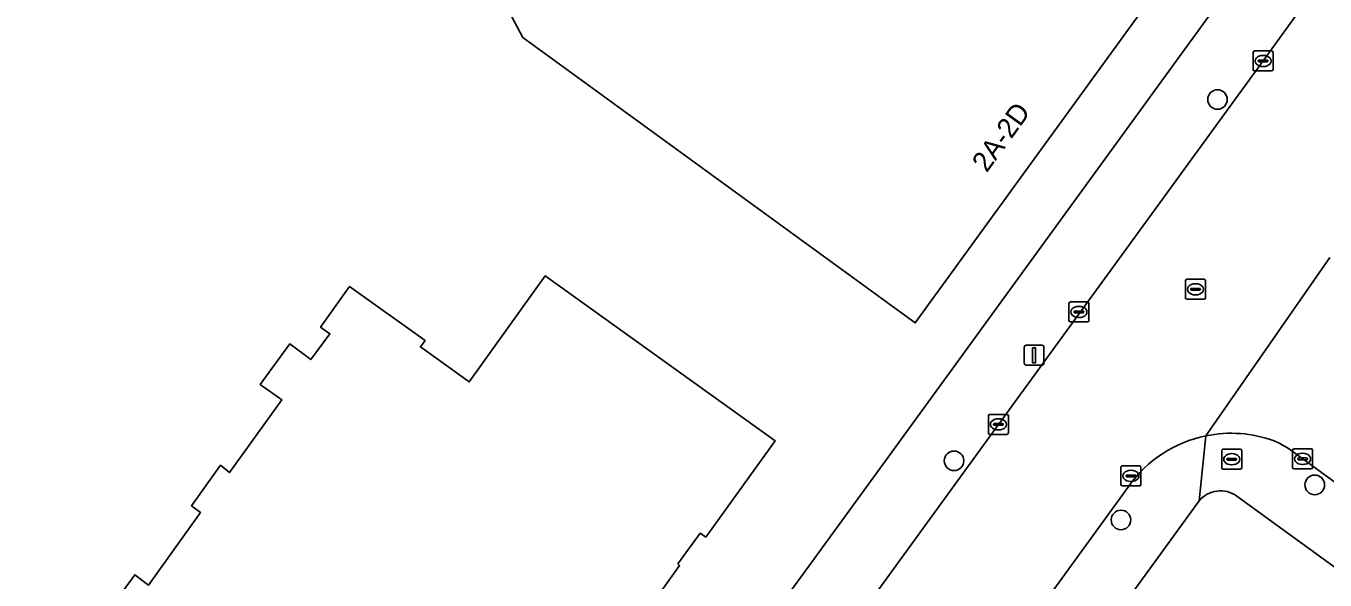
# Model space of a CAD drawing. Extents: x 159674 to 160531, y 382172 to 382904.
# Drawn here: x 160035.6 to 160100.6, y 382566.2 to 382593.8 of the extents above; entities that cross this region are included whole.
import ezdxf

# ---------------------------------------------------------------- set-up
doc = ezdxf.new("R2010")
doc.units = 0
for name, color, linetype in [('IMGEO_Boom', 7, 'Continuous'), ('IMGEO_Brandkraan', 7, 'Continuous'), ('IMGEO_Erf', 7, 'Continuous'), ('IMGEO_Kolk', 7, 'Continuous'), ('IMGEO_Lichtmast', 7, 'Continuous'), ('IMGEO_Pand', 7, 'Continuous'), ('IMGEO_Pand_nummerreeks', 7, 'Continuous'), ('IMGEO_Rijbaan_lokaal_open', 7, 'Continuous'), ('IMGEO_Rioolput', 7, 'Continuous'), ('IMGEO_Voetpad_open', 7, 'Continuous')]:
    doc.layers.add(name, color=color, linetype=linetype)

msp = doc.modelspace()

# ---------------------------------------------------------------- linework, layer by layer
at = {"layer": 'IMGEO_Boom'}
for centre in [(160095.183, 382590.164), (160082.011, 382572.108), (160100.046, 382570.904), (160090.355, 382569.153)]:
    msp.add_circle(centre, 0.489, dxfattribs=at)
at = {"layer": 'IMGEO_Brandkraan'}
for p, q in [((160095.469, 382572.687), (160096.321, 382572.687)), ((160095.394, 382571.761), (160095.394, 382572.613)), ((160095.653, 382572.181), (160095.653, 382572.193)), ((160096.091, 382572.144), (160095.693, 382572.144)), ((160095.696, 382572.23), (160096.094, 382572.23)), ((160095.882, 382572.467), (160095.907, 382572.467)), ((160096.137, 382572.193), (160096.137, 382572.181)), ((160096.395, 382572.613), (160096.395, 382571.761)), ((160096.321, 382571.687), (160095.469, 382571.687)), ((160095.905, 382571.907), (160095.88, 382571.907))]:
    msp.add_line(p, q, dxfattribs=at)
for points in [[(160095.469, 382572.687), (160096.321, 382572.687)], [(160095.394, 382571.761), (160095.394, 382572.613)], [(160096.395, 382572.613), (160096.395, 382571.761)], [(160096.321, 382571.687), (160095.469, 382571.687)]]:
    msp.add_lwpolyline(points, dxfattribs=at)
for centre, radius, start, end in [((160095.471, 382572.611), 0.0765, 91.55205, 178.44795), ((160095.471, 382572.611), 0.0765, 91.55205, 178.44795), ((160096.319, 382572.611), 0.0765, 1.55205, 88.44795), ((160096.319, 382572.611), 0.0765, 1.55205, 88.44795), ((160095.693, 382572.19), 0.0403, 85.87752, 175.75265), ((160095.69, 382572.18), 0.0366, 178.93798, 274.71019), ((160096.094, 382572.187), 0.043, 264.86636, 352.45326), ((160096.098, 382572.192), 0.0386, 1.73085, 96.63898), ((160095.471, 382571.763), 0.0765, 181.55205, 268.44795), ((160095.471, 382571.763), 0.0765, 181.55205, 268.44795), ((160096.319, 382571.763), 0.0765, 271.55205, 358.44795), ((160096.319, 382571.763), 0.0765, 271.55205, 358.44795)]:
    msp.add_arc(centre, radius, start, end, dxfattribs=at)
for centre, major_axis, ratio, start_param, end_param in [((160095.881, 382572.187), (-0.387, 0.002), 0.722429, 4.712389, 7.853982), ((160095.906, 382572.187), (-0.39, 0.002), 0.717154, 1.570796, 4.712389)]:
    msp.add_ellipse(centre, major_axis=major_axis, ratio=ratio, start_param=start_param, end_param=end_param, dxfattribs=at)
at = {"layer": 'IMGEO_Erf'}
for points in [[(159987.625, 382596.74), (159998.32, 382576.572), (160012.158, 382566.305), (160014.085, 382564.875), (160015.556, 382563.784), (160018.977, 382561.245), (160021.814, 382559.14), (160050.522, 382537.716), (160052.445, 382536.281), (160054.378, 382538.936), (160055.599, 382540.613), (160060.131, 382546.714), (160064.26, 382552.334), (160068.989, 382558.995), (160073.24, 382564.766), (160078.977, 382572.654), (160139.025, 382655.211)], [(160093.699, 382597.768), (160080.073, 382579.001), (160060.451, 382593.261), (160043.33, 382625.444)], [(160039.563, 382564.384), (160041.044, 382566.417), (160041.727, 382565.89), (160044.328, 382569.516), (160043.878, 382569.863), (160045.338, 382571.887), (160045.791, 382571.52), (160048.402, 382575.152), (160047.321, 382575.925), (160048.796, 382577.95), (160049.847, 382577.166), (160050.802, 382578.453), (160050.343, 382578.793), (160051.792, 382580.818), (160055.56, 382578.117), (160055.332, 382577.8), (160057.77, 382576.052), (160061.568, 382581.351), (160068.999, 382576.024), (160073.063, 382573.111), (160069.597, 382568.294), (160069.324, 382568.488), (160068.201, 382566.953), (160068.292, 382566.873), (160066.759, 382564.747)], [(160094.261, 382570.107), (160066.611, 382532.056)], [(160106.42, 382540.296), (160101.292, 382544.099), (160102.861, 382546.215), (160104.194, 382548.012), (160109.338, 382544.231), (160111.578, 382547.337), (160108.798, 382549.356), (160109.901, 382550.874), (160111.668, 382551.187), (160113.36, 382549.958), (160113.608, 382550.312), (160108.612, 382553.944), (160110.021, 382555.881), (160115.017, 382552.25), (160117.084, 382555.093), (160117.069, 382555.171), (160096.153, 382570.347)]]:
    msp.add_lwpolyline(points, dxfattribs=at)
msp.add_arc((160095.337, 382569.203), 1.405, 54.50552, 139.95319, dxfattribs=at)
at = {"layer": 'IMGEO_Kolk'}
for p, q in [((160096.962, 382591.663), (160096.962, 382592.515)), ((160097.037, 382592.589), (160097.889, 382592.589)), ((160097.45, 382592.369), (160097.475, 382592.369)), ((160097.963, 382592.515), (160097.963, 382591.663)), ((160097.889, 382591.589), (160097.037, 382591.589)), ((160097.221, 382592.083), (160097.221, 382592.095)), ((160097.659, 382592.046), (160097.261, 382592.046)), ((160097.264, 382592.132), (160097.662, 382592.132)), ((160097.473, 382591.809), (160097.448, 382591.809)), ((160097.705, 382592.095), (160097.705, 382592.083)), ((160087.755, 382579.121), (160087.755, 382579.973)), ((160087.83, 382580.047), (160088.682, 382580.047)), ((160088.243, 382579.827), (160088.268, 382579.827)), ((160088.756, 382579.973), (160088.756, 382579.121)), ((160088.014, 382579.541), (160088.014, 382579.553)), ((160088.452, 382579.504), (160088.054, 382579.504)), ((160088.057, 382579.59), (160088.455, 382579.59)), ((160088.266, 382579.267), (160088.241, 382579.267)), ((160088.498, 382579.553), (160088.498, 382579.541)), ((160088.682, 382579.047), (160087.83, 382579.047)), ((160083.728, 382573.502), (160083.728, 382574.354)), ((160083.803, 382574.428), (160084.655, 382574.428)), ((160084.216, 382574.208), (160084.241, 382574.208)), ((160084.729, 382574.354), (160084.729, 382573.502)), ((160084.655, 382573.428), (160083.803, 382573.428)), ((160083.987, 382573.922), (160083.987, 382573.934)), ((160084.425, 382573.885), (160084.027, 382573.885)), ((160084.03, 382573.971), (160084.428, 382573.971)), ((160084.239, 382573.648), (160084.214, 382573.648)), ((160084.471, 382573.934), (160084.471, 382573.922)), ((160099.013, 382572.705), (160099.865, 382572.705)), ((160098.938, 382571.779), (160098.938, 382572.631)), ((160099.197, 382572.199), (160099.197, 382572.211)), ((160099.635, 382572.162), (160099.237, 382572.162)), ((160099.24, 382572.248), (160099.638, 382572.248)), ((160099.426, 382572.485), (160099.451, 382572.485)), ((160099.681, 382572.211), (160099.681, 382572.199)), ((160099.939, 382572.631), (160099.939, 382571.779)), ((160090.354, 382570.929), (160090.354, 382571.781)), ((160090.429, 382571.855), (160091.281, 382571.855)), ((160090.656, 382571.398), (160091.054, 382571.398)), ((160090.842, 382571.635), (160090.867, 382571.635)), ((160091.355, 382571.781), (160091.355, 382570.929)), ((160099.865, 382571.705), (160099.013, 382571.705)), ((160099.449, 382571.925), (160099.424, 382571.925)), ((160091.281, 382570.855), (160090.429, 382570.855)), ((160090.613, 382571.349), (160090.613, 382571.361)), ((160091.051, 382571.312), (160090.653, 382571.312)), ((160090.865, 382571.075), (160090.84, 382571.075)), ((160091.097, 382571.361), (160091.097, 382571.349))]:
    msp.add_line(p, q, dxfattribs=at)
for points in [[(160096.962, 382591.663), (160096.962, 382592.515)], [(160097.037, 382592.589), (160097.889, 382592.589)], [(160097.963, 382592.515), (160097.963, 382591.663)], [(160097.889, 382591.589), (160097.037, 382591.589)], [(160087.755, 382579.121), (160087.755, 382579.973)], [(160087.83, 382580.047), (160088.682, 382580.047)], [(160088.756, 382579.973), (160088.756, 382579.121)], [(160088.682, 382579.047), (160087.83, 382579.047)], [(160083.728, 382573.502), (160083.728, 382574.354)], [(160083.803, 382574.428), (160084.655, 382574.428)], [(160084.729, 382574.354), (160084.729, 382573.502)], [(160084.655, 382573.428), (160083.803, 382573.428)], [(160099.013, 382572.705), (160099.865, 382572.705)], [(160098.938, 382571.779), (160098.938, 382572.631)], [(160099.939, 382572.631), (160099.939, 382571.779)], [(160090.354, 382570.929), (160090.354, 382571.781)], [(160090.429, 382571.855), (160091.281, 382571.855)], [(160091.355, 382571.781), (160091.355, 382570.929)], [(160099.865, 382571.705), (160099.013, 382571.705)], [(160091.281, 382570.855), (160090.429, 382570.855)]]:
    msp.add_lwpolyline(points, dxfattribs=at)
for centre, radius, start, end in [((160097.039, 382592.513), 0.0765, 91.55205, 178.44795), ((160097.039, 382592.513), 0.0765, 91.55205, 178.44795), ((160097.887, 382592.513), 0.0765, 1.55205, 88.44795), ((160097.887, 382592.513), 0.0765, 1.55205, 88.44795), ((160097.039, 382591.665), 0.0765, 181.55205, 268.44795), ((160097.039, 382591.665), 0.0765, 181.55205, 268.44795), ((160097.261, 382592.092), 0.0403, 85.87752, 175.75265), ((160097.258, 382592.082), 0.0366, 178.93798, 274.71019), ((160097.662, 382592.089), 0.043, 264.86636, 352.45326), ((160097.666, 382592.094), 0.0386, 1.73085, 96.63898), ((160097.887, 382591.665), 0.0765, 271.55205, 358.44795), ((160097.887, 382591.665), 0.0765, 271.55205, 358.44795), ((160087.832, 382579.971), 0.0765, 91.55205, 178.44795), ((160087.832, 382579.971), 0.0765, 91.55205, 178.44795), ((160088.68, 382579.971), 0.0765, 1.55205, 88.44795), ((160088.68, 382579.971), 0.0765, 1.55205, 88.44795), ((160088.054, 382579.55), 0.0403, 85.87752, 175.75265), ((160088.051, 382579.54), 0.0366, 178.93798, 274.71019), ((160088.455, 382579.547), 0.043, 264.86636, 352.45326), ((160088.459, 382579.552), 0.0386, 1.73085, 96.63898), ((160087.832, 382579.123), 0.0765, 181.55205, 268.44795), ((160087.832, 382579.123), 0.0765, 181.55205, 268.44795), ((160088.68, 382579.123), 0.0765, 271.55205, 358.44795), ((160088.68, 382579.123), 0.0765, 271.55205, 358.44795), ((160083.805, 382574.352), 0.0765, 91.55205, 178.44795), ((160083.805, 382574.352), 0.0765, 91.55205, 178.44795), ((160084.653, 382574.352), 0.0765, 1.55205, 88.44795), ((160084.653, 382574.352), 0.0765, 1.55205, 88.44795), ((160083.805, 382573.504), 0.0765, 181.55205, 268.44795), ((160083.805, 382573.504), 0.0765, 181.55205, 268.44795), ((160084.027, 382573.931), 0.0403, 85.87752, 175.75265), ((160084.024, 382573.921), 0.0366, 178.93798, 274.71019), ((160084.428, 382573.928), 0.043, 264.86636, 352.45326), ((160084.432, 382573.933), 0.0386, 1.73085, 96.63898), ((160084.653, 382573.504), 0.0765, 271.55205, 358.44795), ((160084.653, 382573.504), 0.0765, 271.55205, 358.44795), ((160099.015, 382572.629), 0.0765, 91.55205, 178.44795), ((160099.015, 382572.629), 0.0765, 91.55205, 178.44795), ((160099.863, 382572.629), 0.0765, 1.55205, 88.44795), ((160099.863, 382572.629), 0.0765, 1.55205, 88.44795), ((160099.237, 382572.208), 0.0403, 85.87752, 175.75265), ((160099.234, 382572.198), 0.0366, 178.93798, 274.71019), ((160099.638, 382572.205), 0.043, 264.86636, 352.45326), ((160099.642, 382572.21), 0.0386, 1.73085, 96.63898), ((160090.431, 382571.779), 0.0765, 91.55205, 178.44795), ((160090.431, 382571.779), 0.0765, 91.55205, 178.44795), ((160090.653, 382571.358), 0.0403, 85.87752, 175.75265), ((160091.058, 382571.36), 0.0386, 1.73085, 96.63898), ((160091.279, 382571.779), 0.0765, 1.55205, 88.44795), ((160091.279, 382571.779), 0.0765, 1.55205, 88.44795), ((160099.015, 382571.781), 0.0765, 181.55205, 268.44795), ((160099.015, 382571.781), 0.0765, 181.55205, 268.44795), ((160099.863, 382571.781), 0.0765, 271.55205, 358.44795), ((160099.863, 382571.781), 0.0765, 271.55205, 358.44795), ((160090.431, 382570.931), 0.0765, 181.55205, 268.44795), ((160090.431, 382570.931), 0.0765, 181.55205, 268.44795), ((160090.65, 382571.348), 0.0366, 178.93798, 274.71019), ((160091.054, 382571.355), 0.043, 264.86636, 352.45326), ((160091.279, 382570.931), 0.0765, 271.55205, 358.44795), ((160091.279, 382570.931), 0.0765, 271.55205, 358.44795)]:
    msp.add_arc(centre, radius, start, end, dxfattribs=at)
for centre, major_axis, ratio, start_param, end_param in [((160097.449, 382592.089), (-0.387, 0.002), 0.722429, 4.712389, 7.853982), ((160097.474, 382592.089), (-0.39, 0.002), 0.717154, 1.570796, 4.712389), ((160088.242, 382579.547), (-0.387, 0.002), 0.722429, 4.712389, 7.853982), ((160088.267, 382579.547), (-0.39, 0.002), 0.717154, 1.570796, 4.712389), ((160084.215, 382573.928), (-0.387, 0.002), 0.722429, 4.712389, 7.853982), ((160084.24, 382573.928), (-0.39, 0.002), 0.717154, 1.570796, 4.712389), ((160099.425, 382572.205), (-0.387, 0.002), 0.722429, 4.712389, 7.853982), ((160099.45, 382572.205), (-0.39, 0.002), 0.717154, 1.570796, 4.712389), ((160090.841, 382571.355), (-0.387, 0.002), 0.722429, 4.712389, 7.853982), ((160090.866, 382571.355), (-0.39, 0.002), 0.717154, 1.570796, 4.712389)]:
    msp.add_ellipse(centre, major_axis=major_axis, ratio=ratio, start_param=start_param, end_param=end_param, dxfattribs=at)
at = {"layer": 'IMGEO_Lichtmast'}
for p, q in [((160085.617, 382577.885), (160086.407, 382577.885)), ((160086.407, 382577.885), (160085.617, 382577.885)), ((160085.517, 382576.985), (160085.517, 382577.785)), ((160085.517, 382577.785), (160085.517, 382576.985)), ((160086.507, 382577.785), (160086.507, 382576.985)), ((160086.507, 382576.985), (160086.507, 382577.785)), ((160086.407, 382576.885), (160085.617, 382576.885)), ((160085.617, 382576.885), (160086.407, 382576.885))]:
    msp.add_line(p, q, dxfattribs=at)
msp.add_lwpolyline([(160085.937, 382577.76), (160086.087, 382577.76), (160086.087, 382577.01), (160085.937, 382577.01), (160085.937, 382577.76)], dxfattribs=at)
for centre, start, end in [((160085.617, 382577.785), 90, 180), ((160085.617, 382577.785), 90, 180), ((160086.407, 382577.785), 0, 90), ((160086.407, 382577.785), 360, 90), ((160085.617, 382576.985), 180, 270), ((160085.617, 382576.985), 180, 270), ((160086.407, 382576.985), 270, 0), ((160086.407, 382576.985), 270, 0)]:
    msp.add_arc(centre, 0.1, start, end, dxfattribs=at)
at = {"layer": 'IMGEO_Pand'}
msp.add_lwpolyline([(160072.549, 382611.154), (160070.567, 382614.879), (160071.817, 382615.545), (160061.423, 382635.078), (160053.878, 382631.061), (160052.635, 382630.399), (160043.33, 382625.444), (160060.451, 382593.261), (160080.073, 382579.001), (160093.699, 382597.768), (160077.262, 382609.692), (160076.333, 382608.411)], close=True, dxfattribs=at)
msp.add_lwpolyline([(160066.759, 382564.747), (160068.292, 382566.873), (160068.201, 382566.953), (160069.324, 382568.488), (160069.597, 382568.294), (160073.063, 382573.111), (160068.999, 382576.024), (160061.568, 382581.351), (160057.77, 382576.052), (160055.332, 382577.8), (160055.56, 382578.117), (160051.792, 382580.818), (160050.343, 382578.793), (160050.802, 382578.453), (160049.847, 382577.166), (160048.796, 382577.95), (160047.321, 382575.925), (160048.402, 382575.152), (160045.791, 382571.52), (160045.338, 382571.887), (160043.878, 382569.863), (160044.328, 382569.516), (160041.727, 382565.89), (160041.044, 382566.417), (160039.563, 382564.384)], dxfattribs=at)
at = {"layer": 'IMGEO_Rijbaan_lokaal_open'}
for points in [[(160102.443, 382586.988), (160126.918, 382620.636), (160127.333, 382621.232), (160121.569, 382625.329), (160121.488, 382625.214), (160109.443, 382608.67), (160097.463, 382592.089), (160084.229, 382573.928), (160076.311, 382563.035), (160076.064, 382562.694), (160071.89, 382556.928), (160067.829, 382551.317), (160067.089, 382550.301), (160063.381, 382545.206), (160061.047, 382541.977), (160060.192, 382540.757), (160059.002, 382539.131), (160063.104, 382536.111)], [(160094.604, 382573.357), (160100.791, 382582.263)], [(160100.791, 382582.263), (160094.604, 382573.357)], [(160098.735, 382572.717), (160106.361, 382567.175), (160110.485, 382572.841), (160103.182, 382578.158)], [(160066.449, 382537.355), (160066.557, 382537.532), (160082.411, 382559.366), (160090.741, 382570.837)]]:
    msp.add_lwpolyline(points, dxfattribs=at)
for centre, radius, start, end in [((160095.867, 382567.2), 6.285, 101.59179, 144.64447), ((160095.865, 382567.208), 6.277, 69.96043, 101.59152), ((160095.475, 382567.537), 6.121, 57.82015, 65.47385)]:
    msp.add_arc(centre, radius, start, end, dxfattribs=at)
at = {"layer": 'IMGEO_Rioolput'}
for p, q in [((160093.658, 382581.179), (160094.51, 382581.179)), ((160093.583, 382580.253), (160093.583, 382581.105)), ((160093.842, 382580.673), (160093.842, 382580.685)), ((160094.28, 382580.636), (160093.882, 382580.636)), ((160093.885, 382580.722), (160094.283, 382580.722)), ((160094.071, 382580.959), (160094.096, 382580.959)), ((160094.326, 382580.685), (160094.326, 382580.673)), ((160094.584, 382581.105), (160094.584, 382580.253)), ((160094.51, 382580.179), (160093.658, 382580.179)), ((160094.094, 382580.399), (160094.069, 382580.399))]:
    msp.add_line(p, q, dxfattribs=at)
for points in [[(160093.658, 382581.179), (160094.51, 382581.179)], [(160093.583, 382580.253), (160093.583, 382581.105)], [(160094.584, 382581.105), (160094.584, 382580.253)], [(160094.51, 382580.179), (160093.658, 382580.179)]]:
    msp.add_lwpolyline(points, dxfattribs=at)
for centre, radius, start, end in [((160093.66, 382581.103), 0.0765, 91.55205, 178.44795), ((160093.66, 382581.103), 0.0765, 91.55205, 178.44795), ((160094.508, 382581.103), 0.0765, 1.55205, 88.44795), ((160094.508, 382581.103), 0.0765, 1.55205, 88.44795), ((160093.882, 382580.682), 0.0403, 85.87752, 175.75265), ((160093.879, 382580.672), 0.0366, 178.93798, 274.71019), ((160094.283, 382580.679), 0.043, 264.86636, 352.45326), ((160094.287, 382580.684), 0.0386, 1.73085, 96.63898), ((160093.66, 382580.255), 0.0765, 181.55205, 268.44795), ((160093.66, 382580.255), 0.0765, 181.55205, 268.44795), ((160094.508, 382580.255), 0.0765, 271.55205, 358.44795), ((160094.508, 382580.255), 0.0765, 271.55205, 358.44795)]:
    msp.add_arc(centre, radius, start, end, dxfattribs=at)
for centre, major_axis, ratio, start_param, end_param in [((160094.07, 382580.679), (-0.387, 0.002), 0.722429, 4.712389, 7.853982), ((160094.095, 382580.679), (-0.39, 0.002), 0.717154, 1.570796, 4.712389)]:
    msp.add_ellipse(centre, major_axis=major_axis, ratio=ratio, start_param=start_param, end_param=end_param, dxfattribs=at)
at = {"layer": 'IMGEO_Voetpad_open'}
for points in [[(160160.682, 382684.114), (160158.819, 382681.732), (160139.364, 382654.969), (160139.025, 382655.211), (160078.977, 382572.654), (160073.24, 382564.766), (160076.064, 382562.694), (160076.311, 382563.035), (160084.229, 382573.928), (160097.463, 382592.089), (160109.443, 382608.67), (160121.488, 382625.214), (160121.569, 382625.329), (160133.916, 382642.352), (160134.723, 382643.445), (160146.792, 382660.104), (160161.775, 382680.602)], [(160094.261, 382570.107), (160094.604, 382573.357)], [(160094.604, 382573.357), (160094.261, 382570.107)], [(160166.836, 382523.227), (160164.514, 382524.914), (160108.691, 382565.482), (160106.361, 382567.175), (160098.735, 382572.717)], [(160090.741, 382570.837), (160082.411, 382559.366), (160066.557, 382537.532), (160066.449, 382537.355)], [(160062.083, 382531.152), (160066.611, 382532.056), (160094.261, 382570.107)], [(160096.153, 382570.347), (160117.069, 382555.171), (160117.084, 382555.093), (160117.459, 382553.168)]]:
    msp.add_lwpolyline(points, dxfattribs=at)
for centre, radius, start, end in [((160095.867, 382567.2), 6.285, 101.59179, 144.64447), ((160095.865, 382567.208), 6.277, 69.96043, 101.59152), ((160095.475, 382567.537), 6.121, 57.82015, 65.47385), ((160095.337, 382569.203), 1.405, 54.50552, 139.95319)]:
    msp.add_arc(centre, radius, start, end, dxfattribs=at)

# ---------------------------------------------------------------- texts
at = {"layer": 'IMGEO_Pand_nummerreeks'}
msp.add_text('2A-2D', height=1, rotation=54.01846, dxfattribs=at).set_placement((160083.645, 382586.473))

doc.saveas('drawing.dxf')
